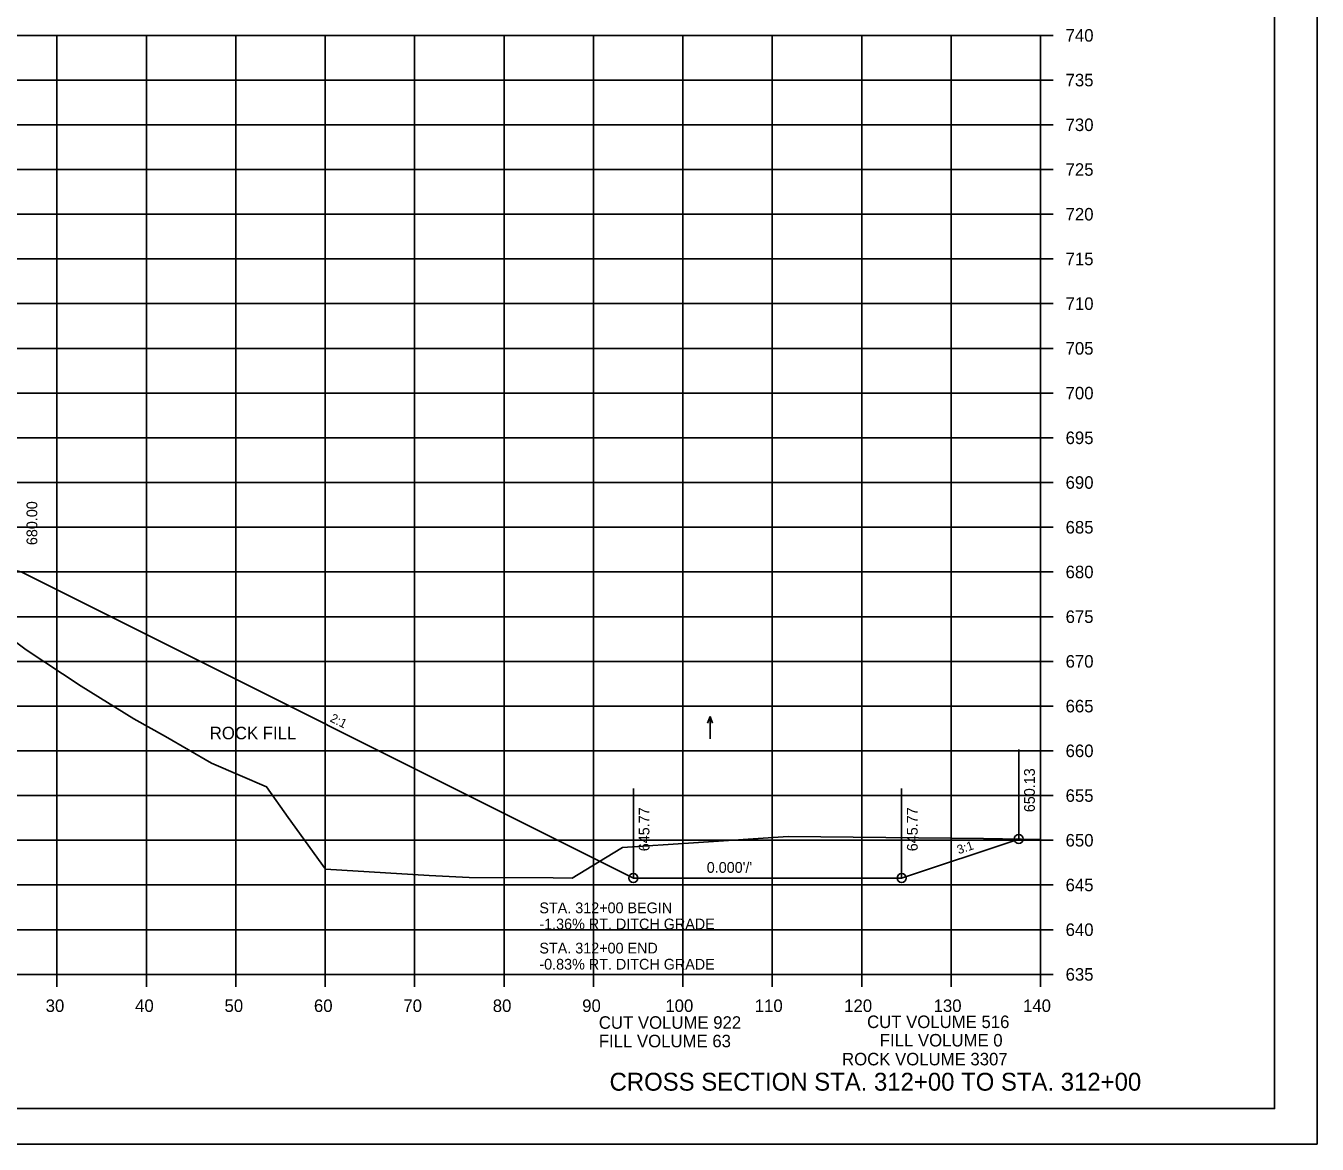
# Model space of a CAD drawing. Extents: x 1370515 to 1370849, y 383299 to 386073.
# Drawn here: x 1370704.3 to 1370848.7, y 385219.5 to 385344.5 of the extents above; entities that cross this region are included whole.
import ezdxf

# ---------------------------------------------------------------- set-up
doc = ezdxf.new("R2010")
doc.units = 0
for name, color, linetype in [('R_Axis', 7, 'Continuous'), ('R_Axis Annot', 7, 'Continuous'), ('R_Border', 7, 'Continuous'), ('R_Draft', 7, 'Continuous'), ('R_Drive', 7, 'Continuous'), ('R_Exist Surface', 7, 'Continuous'), ('R_Fin Surface', 7, 'Continuous'), ('R_Grid', 7, 'Continuous'), ('R_No Plot', 7, 'Continuous'), ('R_Water Annot', 7, 'Continuous'), ('R_Xsect Elev', 7, 'Continuous'), ('R_Xsect Slope', 7, 'Continuous')]:
    doc.layers.add(name, color=color, linetype=linetype)

msp = doc.modelspace()

# ---------------------------------------------------------------- linework, layer by layer
at = {"layer": 'R_Axis'}
for p, q in [((1370819.2, 385343.45), (1370816.4, 385343.45)), ((1370817.8, 385238.45), (1370817.8, 385343.45)), ((1370819.2, 385338.45), (1370816.4, 385338.45)), ((1370819.2, 385333.45), (1370816.4, 385333.45)), ((1370819.2, 385328.45), (1370816.4, 385328.45)), ((1370819.2, 385323.45), (1370816.4, 385323.45)), ((1370819.2, 385318.45), (1370816.4, 385318.45)), ((1370819.2, 385313.45), (1370816.4, 385313.45)), ((1370819.2, 385308.45), (1370816.4, 385308.45)), ((1370819.2, 385303.45), (1370816.4, 385303.45)), ((1370819.2, 385298.45), (1370816.4, 385298.45)), ((1370819.2, 385293.45), (1370816.4, 385293.45)), ((1370819.2, 385288.45), (1370816.4, 385288.45)), ((1370819.2, 385283.45), (1370816.4, 385283.45)), ((1370819.2, 385278.45), (1370816.4, 385278.45)), ((1370819.2, 385273.45), (1370816.4, 385273.45)), ((1370819.2, 385268.45), (1370816.4, 385268.45)), ((1370819.2, 385263.45), (1370816.4, 385263.45)), ((1370819.2, 385258.45), (1370816.4, 385258.45)), ((1370819.2, 385253.45), (1370816.4, 385253.45)), ((1370819.2, 385248.45), (1370816.4, 385248.45)), ((1370819.2, 385243.45), (1370816.4, 385243.45)), ((1370707.8, 385237.05), (1370707.8, 385239.85)), ((1370717.8, 385237.05), (1370717.8, 385239.85)), ((1370727.8, 385237.05), (1370727.8, 385239.85)), ((1370737.8, 385237.05), (1370737.8, 385239.85)), ((1370747.8, 385237.05), (1370747.8, 385239.85)), ((1370757.8, 385237.05), (1370757.8, 385239.85)), ((1370767.8, 385237.05), (1370767.8, 385239.85)), ((1370777.8, 385237.05), (1370777.8, 385239.85)), ((1370787.8, 385237.05), (1370787.8, 385239.85)), ((1370797.8, 385237.05), (1370797.8, 385239.85)), ((1370807.8, 385237.05), (1370807.8, 385239.85)), ((1370817.8, 385237.05), (1370817.8, 385239.85)), ((1370537.8, 385238.45), (1370817.8, 385238.45)), ((1370819.2, 385238.45), (1370816.4, 385238.45))]:
    msp.add_line(p, q, dxfattribs=at)
at = {"layer": 'R_Border'}
for q in [(1370843.98, 385428.91), (1370527.8, 385223.45)]:
    msp.add_line((1370843.98, 385223.45), q, dxfattribs=at)
at = {"layer": 'R_Exist Surface'}
msp.add_lwpolyline([(1370695.86, 385281.1), (1370704.37, 385274.76), (1370710.52, 385270.67), (1370716.38, 385267.01), (1370719.95, 385265.05), (1370725.1, 385262.08), (1370728.28, 385260.7), (1370731.24, 385259.41), (1370733.67, 385256), (1370737.84, 385250.22), (1370749.42, 385249.51), (1370753.91, 385249.28), (1370763.29, 385249.23), (1370765.43, 385249.22), (1370770.02, 385252.01), (1370771.04, 385252.63), (1370778.99, 385253.16), (1370789.57, 385253.87), (1370811.41, 385253.66), (1370817.8, 385253.54)], dxfattribs=at)
at = {"layer": 'R_Fin Surface'}
msp.add_lwpolyline([(1370583.36, 385315.46), (1370623.38, 385295.45), (1370628.38, 385295.45), (1370631.93, 385281.25), (1370641.93, 385281.25), (1370651.8, 385284.54), (1370657.8, 385286.04), (1370665.8, 385285.82), (1370677.8, 385285.5), (1370689.8, 385285.17), (1370697.8, 385284.95), (1370703.8, 385283.45), (1370772.26, 385249.22), (1370802.26, 385249.22), (1370815.36, 385253.59)], dxfattribs=at)
at = {"layer": 'R_Grid'}
for p, q in [((1370537.8, 385343.45), (1370817.8, 385343.45)), ((1370707.8, 385238.45), (1370707.8, 385343.45)), ((1370717.8, 385238.45), (1370717.8, 385343.45)), ((1370727.8, 385238.45), (1370727.8, 385343.45)), ((1370737.8, 385238.45), (1370737.8, 385343.45)), ((1370747.8, 385238.45), (1370747.8, 385343.45)), ((1370757.8, 385238.45), (1370757.8, 385343.45)), ((1370767.8, 385238.45), (1370767.8, 385343.45)), ((1370777.8, 385238.45), (1370777.8, 385343.45)), ((1370787.8, 385238.45), (1370787.8, 385343.45)), ((1370797.8, 385238.45), (1370797.8, 385343.45)), ((1370807.8, 385238.45), (1370807.8, 385343.45)), ((1370817.8, 385238.45), (1370817.8, 385343.45)), ((1370537.8, 385338.45), (1370817.8, 385338.45)), ((1370537.8, 385333.45), (1370817.8, 385333.45)), ((1370537.8, 385328.45), (1370817.8, 385328.45)), ((1370537.8, 385323.45), (1370817.8, 385323.45)), ((1370537.8, 385318.45), (1370817.8, 385318.45)), ((1370537.8, 385313.45), (1370817.8, 385313.45)), ((1370537.8, 385308.45), (1370817.8, 385308.45)), ((1370537.8, 385303.45), (1370817.8, 385303.45)), ((1370537.8, 385298.45), (1370817.8, 385298.45)), ((1370537.8, 385293.45), (1370817.8, 385293.45)), ((1370537.8, 385288.45), (1370817.8, 385288.45)), ((1370537.8, 385283.45), (1370817.8, 385283.45)), ((1370537.8, 385278.45), (1370817.8, 385278.45)), ((1370537.8, 385273.45), (1370817.8, 385273.45)), ((1370537.8, 385268.45), (1370817.8, 385268.45)), ((1370537.8, 385263.45), (1370817.8, 385263.45)), ((1370537.8, 385258.45), (1370817.8, 385258.45)), ((1370537.8, 385253.45), (1370817.8, 385253.45)), ((1370537.8, 385248.45), (1370817.8, 385248.45)), ((1370537.8, 385243.45), (1370817.8, 385243.45)), ((1370537.8, 385238.45), (1370817.8, 385238.45))]:
    msp.add_line(p, q, dxfattribs=at)
at = {"layer": 'R_No Plot'}
msp.add_line((1370515.4, 385219.47), (1370848.73, 385219.47), dxfattribs=at)
for points in [[(1370515.39, 385432.81), (1370848.73, 385432.81), (1370848.73, 385219.47), (1370515.39, 385219.47)], [(1370761.72, 385428.91), (1370761.72, 385419.03), (1370797.45, 385419.03), (1370797.45, 385416.11), (1370820.65, 385416.11), (1370820.65, 385392.9), (1370843.98, 385392.9), (1370843.98, 385223.45), (1370527.8, 385223.45), (1370527.8, 385428.91)]]:
    msp.add_lwpolyline(points, close=True, dxfattribs=at)
for centre in [(1370815.36, 385253.59), (1370772.26, 385249.22), (1370772.26, 385249.22), (1370802.26, 385249.22)]:
    msp.add_circle(centre, 0.5, dxfattribs=at)
at = {"layer": 'R_Water Annot'}
for p, q in [((1370780.84, 385267.3), (1370780.56, 385266.53)), ((1370780.84, 385264.79), (1370780.84, 385267.3)), ((1370780.84, 385267.3), (1370781.12, 385266.53))]:
    msp.add_line(p, q, dxfattribs=at)
at = {"layer": 'R_Xsect Elev'}
for p, q in [((1370815.36, 385253.59), (1370815.36, 385263.59)), ((1370772.26, 385249.22), (1370772.26, 385259.22)), ((1370802.26, 385249.22), (1370802.26, 385259.22))]:
    msp.add_line(p, q, dxfattribs=at)

# ---------------------------------------------------------------- texts
at = {"layer": 'R_Axis Annot'}
for s, p in [('740', (1370820.6, 385342.75)), ('735', (1370820.6, 385337.75)), ('730', (1370820.6, 385332.75)), ('725', (1370820.6, 385327.75)), ('720', (1370820.6, 385322.75)), ('715', (1370820.6, 385317.75)), ('710', (1370820.6, 385312.75)), ('705', (1370820.6, 385307.75)), ('700', (1370820.6, 385302.75)), ('695', (1370820.6, 385297.75)), ('690', (1370820.6, 385292.75)), ('685', (1370820.6, 385287.75)), ('680', (1370820.6, 385282.75)), ('675', (1370820.6, 385277.75)), ('670', (1370820.6, 385272.75)), ('665', (1370820.6, 385267.75)), ('ROCK FILL', (1370724.89, 385264.74)), ('660', (1370820.6, 385262.75)), ('655', (1370820.6, 385257.75)), ('650', (1370820.6, 385252.75)), ('645', (1370820.6, 385247.75)), ('640', (1370820.6, 385242.75)), ('635', (1370820.6, 385237.75)), ('30', (1370706.54, 385234.25)), ('40', (1370716.54, 385234.25)), ('50', (1370726.54, 385234.25)), ('60', (1370736.54, 385234.25)), ('70', (1370746.54, 385234.25)), ('80', (1370756.54, 385234.25)), ('90', (1370766.54, 385234.25)), ('100', (1370775.84, 385234.25)), ('110', (1370785.84, 385234.25)), ('120', (1370795.84, 385234.25)), ('130', (1370805.84, 385234.25)), ('140', (1370815.84, 385234.25)), ('CUT VOLUME 922', (1370768.4, 385232.37)), ('CUT VOLUME 516', (1370798.4, 385232.45)), ('FILL VOLUME 63', (1370768.4, 385230.3)), ('FILL VOLUME 0', (1370799.82, 385230.39)), ('ROCK VOLUME 3307', (1370795.6, 385228.28))]:
    msp.add_text(s, height=1.4, dxfattribs=at).set_placement(p)
at = {"layer": 'R_Draft'}
msp.add_text('CROSS SECTION STA. 312+00 TO STA. 312+00', height=2, dxfattribs=at).set_placement((1370769.6, 385225.45))
at = {"layer": 'R_Drive'}
for s, p in [('STA. 312+00 BEGIN', (1370761.75, 385245.29)), ('-1.36% RT. DITCH GRADE', (1370761.75, 385243.49)), ('STA. 312+00 END', (1370761.75, 385240.79)), ('-0.83% RT. DITCH GRADE', (1370761.75, 385238.99))]:
    msp.add_text(s, height=1.2, dxfattribs=at).set_placement(p)
at = {"layer": 'R_No Plot'}
for p in [(1370704.33, 385274.71), (1370716.34, 385266.96), (1370725.06, 385262.03), (1370731.19, 385259.36), (1370771, 385252.58), (1370789.52, 385253.82), (1370737.8, 385250.17), (1370753.87, 385249.23), (1370765.39, 385249.17)]:
    msp.add_text('+', height=0.1, dxfattribs=at).set_placement(p)
at = {"layer": 'R_Xsect Elev'}
for s, p in [('680.00', (1370705.6, 385286.45)), ('650.13', (1370817.16, 385256.59)), ('645.77', (1370774.06, 385252.22)), ('645.77', (1370804.06, 385252.22))]:
    msp.add_text(s, height=1.2, rotation=90, dxfattribs=at).set_placement(p)
at = {"layer": 'R_Xsect Slope'}
for s, rotation, p in [('2:1', 333.4349, (1370738.25, 385266.78)), ('3:1', 18.4349, (1370808.65, 385251.88))]:
    msp.add_text(s, height=1, rotation=rotation, dxfattribs=at).set_placement(p)
msp.add_text("0.000'/'", height=1.2, dxfattribs=at).set_placement((1370780.47, 385249.81))

doc.saveas('drawing.dxf')
